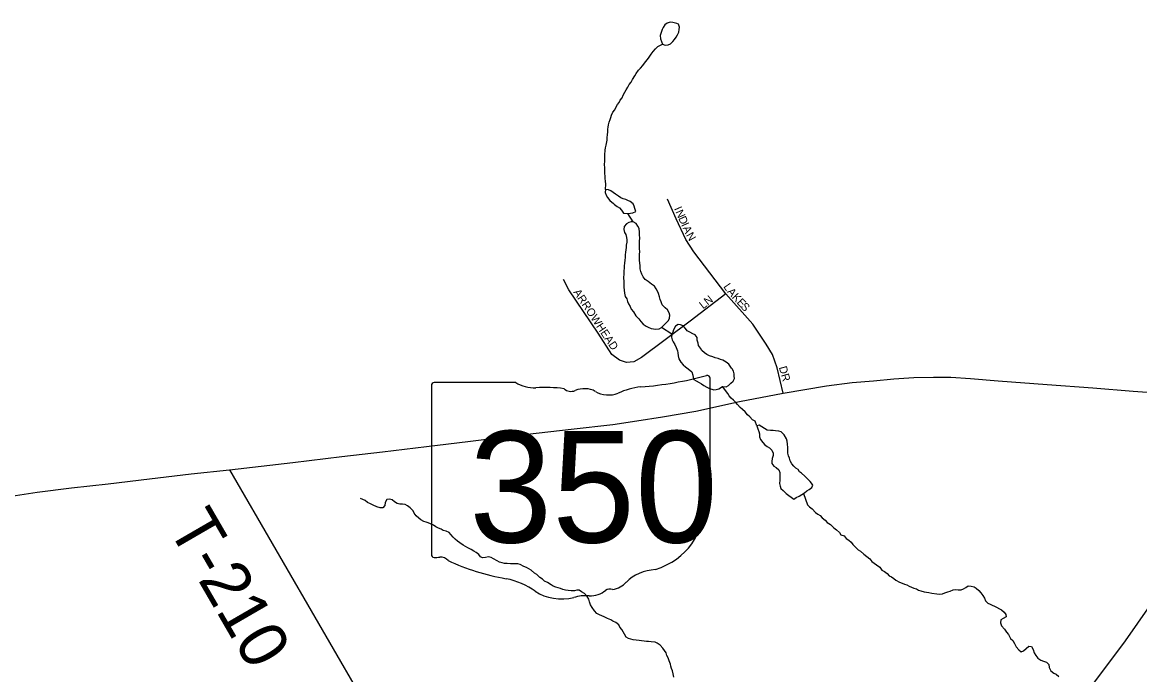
# Model space of a CAD drawing. Extents: x 0.4 to 34.4, y -2.1 to 19.9.
# Drawn here: x 7.097 to 8.419, y 12.657 to 13.429 of the extents above; entities that cross this region are included whole.
import ezdxf

# ---------------------------------------------------------------- set-up
doc = ezdxf.new("R2010")
doc.units = 0
for name, color, linetype in [('GM_X_Minor_Lake', 7, 'Continuous'), ('GM_X_Minor_River', 7, 'Continuous'), ('GM_X_State_Route', 7, 'Continuous'), ('GM_X_State_Shield', 7, 'Continuous'), ('GM_X_Township_Road', 7, 'Continuous'), ('GM_X_Township_Road_Text', 7, 'Continuous'), ('GM_X_Township_Subdivision', 7, 'Continuous'), ('GM_X_Township_Subdivision_Text', 7, 'Continuous'), ('GM_X_US_Route', 7, 'Continuous')]:
    doc.layers.add(name, color=color, linetype=linetype)

msp = doc.modelspace()

# ---------------------------------------------------------------- linework, layer by layer
at = {"layer": 'GM_X_Minor_Lake'}
msp.add_line((7.8082, 13.2034), (7.8131, 13.203), dxfattribs=at)
for points in [[(7.8714, 13.4279), (7.8666, 13.4291), (7.8632, 13.4292), (7.8597, 13.4281), (7.857, 13.4262), (7.855, 13.4232), (7.8538, 13.4206), (7.8526, 13.4172), (7.8514, 13.4134), (7.8521, 13.4096), (7.8542, 13.4035)], [(7.8542, 13.4035), (7.8576, 13.4023), (7.8611, 13.4026), (7.8638, 13.4037), (7.8665, 13.4063), (7.8684, 13.4089), (7.8704, 13.4115), (7.872, 13.4145), (7.8736, 13.4176), (7.8741, 13.4206), (7.8745, 13.4236), (7.8731, 13.4271), (7.8714, 13.4279)], [(7.8131, 13.203), (7.8165, 13.2033), (7.8192, 13.2036), (7.8227, 13.2054), (7.8216, 13.2089), (7.8209, 13.2116), (7.8195, 13.2143), (7.8161, 13.217), (7.8134, 13.2182), (7.8108, 13.2194), (7.8078, 13.2202), (7.8051, 13.2214), (7.8021, 13.2233), (7.7987, 13.226), (7.7961, 13.2276), (7.7931, 13.2296), (7.7905, 13.2311), (7.7867, 13.2312), (7.7866, 13.2278), (7.7877, 13.2247), (7.7891, 13.2217), (7.7921, 13.2182), (7.7964, 13.2147)], [(7.7964, 13.2147), (7.7977, 13.2135), (7.8007, 13.2112), (7.8033, 13.2096), (7.8056, 13.2069), (7.8082, 13.2034)], [(7.8622, 13.0854), (7.8601, 13.0891), (7.8575, 13.0914), (7.8541, 13.0949), (7.8527, 13.0984), (7.8516, 13.1011), (7.8509, 13.1045), (7.8495, 13.1083), (7.8484, 13.111), (7.8469, 13.1137), (7.8447, 13.1168), (7.8413, 13.1195), (7.8372, 13.1226), (7.8338, 13.125), (7.8316, 13.1281), (7.8298, 13.1311), (7.8287, 13.1342), (7.828, 13.1376), (7.8277, 13.1411), (7.8274, 13.1445), (7.8271, 13.1472), (7.8272, 13.1513), (7.8269, 13.1544), (7.8273, 13.1578), (7.827, 13.1612), (7.8271, 13.1647), (7.8272, 13.1704), (7.8273, 13.1738), (7.827, 13.1776), (7.8271, 13.181), (7.8268, 13.1852), (7.8253, 13.1879), (7.8231, 13.191), (7.8197, 13.1929), (7.8171, 13.193), (7.8144, 13.1923), (7.8117, 13.1908), (7.8089, 13.1874), (7.8085, 13.184), (7.8092, 13.1806), (7.811, 13.1779), (7.8117, 13.1745), (7.812, 13.1718), (7.812, 13.1691), (7.8115, 13.1653), (7.8114, 13.1627), (7.811, 13.16), (7.8105, 13.157), (7.8101, 13.1539), (7.81, 13.1513), (7.8096, 13.1475), (7.8095, 13.1444), (7.809, 13.1406), (7.809, 13.138), (7.8085, 13.1353), (7.8084, 13.1319), (7.8083, 13.1266), (7.8086, 13.1228), (7.8085, 13.1186), (7.8085, 13.1159), (7.8088, 13.1121), (7.8094, 13.1087), (7.8101, 13.1049), (7.812, 13.1018), (7.813, 13.0987), (7.8141, 13.096), (7.816, 13.093), (7.8174, 13.0899), (7.82, 13.0864), (7.8229, 13.0818), (7.8263, 13.0783), (7.8285, 13.0752), (7.8315, 13.0721), (7.8349, 13.0698), (7.8375, 13.0686), (7.8409, 13.067), (7.8436, 13.0666), (7.8462, 13.0662), (7.8504, 13.0665), (7.8531, 13.0679)], [(7.8531, 13.0679), (7.8613, 13.0762), (7.8625, 13.0792), (7.863, 13.0826), (7.8622, 13.0854)], [(7.9361, 13.02), (7.9326, 13.0246), (7.9296, 13.027), (7.9258, 13.0293), (7.9228, 13.0301), (7.9202, 13.0313), (7.9168, 13.0321), (7.9137, 13.0333), (7.91, 13.0346), (7.9066, 13.0361), (7.9039, 13.0381), (7.9009, 13.0408), (7.8991, 13.0435), (7.8969, 13.0466), (7.8966, 13.0493), (7.8955, 13.0531), (7.8952, 13.0561), (7.893, 13.0592), (7.8903, 13.0604), (7.8866, 13.0624), (7.8835, 13.0639), (7.8817, 13.067), (7.8787, 13.0701), (7.8757, 13.0713), (7.873, 13.0717), (7.8696, 13.0695), (7.8672, 13.0654), (7.8664, 13.0627), (7.8655, 13.0601), (7.8651, 13.0567), (7.8658, 13.0536), (7.8669, 13.0509), (7.8687, 13.0479), (7.8705, 13.0444), (7.872, 13.0406), (7.8723, 13.0379), (7.873, 13.0345), (7.8737, 13.031), (7.8759, 13.0272), (7.8788, 13.0237), (7.8814, 13.0214), (7.8848, 13.019), (7.8889, 13.0155), (7.89, 13.0117), (7.8907, 13.009), (7.8914, 13.0064), (7.894, 13.0048), (7.8978, 13.0028), (7.9004, 13.0012), (7.9031, 12.9993), (7.9068, 12.9973), (7.9098, 12.9957), (7.9125, 12.9949), (7.9151, 12.9941), (7.9178, 12.9945), (7.9209, 12.9955), (7.9251, 12.9981), (7.9297, 12.9977)], [(7.9297, 12.9977), (7.9324, 12.9995), (7.9352, 13.0021), (7.9379, 13.0044), (7.9395, 13.0078), (7.9392, 13.0104), (7.9392, 13.0131), (7.9381, 13.0165), (7.9367, 13.0192), (7.9361, 13.02)], [(8.029, 12.8858), (8.0226, 12.8921), (8.0189, 12.8956), (8.0163, 12.8972), (8.0148, 12.8999), (8.0122, 12.9014), (8.0096, 12.9041), (8.0073, 12.9068), (8.0055, 12.9103), (8.0044, 12.9134), (8.0034, 12.916), (8.0027, 12.9195), (8.0027, 12.9221), (8.0024, 12.926), (8.0021, 12.9298), (8.0018, 12.9336), (8.0011, 12.9363), (7.9982, 12.9409), (7.9948, 12.9444), (7.9918, 12.9452), (7.988, 12.9456), (7.9854, 12.9461), (7.9819, 12.9461), (7.9781, 12.9466), (7.9751, 12.9485), (7.9717, 12.9505), (7.9687, 12.9524), (7.966, 12.9517), (7.9671, 12.9483), (7.9682, 12.9448), (7.9689, 12.9422), (7.9692, 12.9387), (7.9702, 12.9353), (7.9728, 12.9318), (7.9754, 12.9291), (7.9781, 12.9272), (7.9807, 12.9256), (7.9837, 12.9229), (7.9851, 12.9194), (7.9851, 12.9164), (7.9842, 12.913), (7.9838, 12.9096), (7.9837, 12.9069), (7.9859, 12.9038), (7.9889, 12.9022), (7.9919, 12.8995), (7.993, 12.8965), (7.9933, 12.8938), (7.9933, 12.8907), (7.9932, 12.8873), (7.9927, 12.8835), (7.9934, 12.8801), (7.9941, 12.8774), (7.9971, 12.8751), (8.0005, 12.8716), (8.0095, 12.865)], [(8.0222, 12.8723), (8.0249, 12.8746), (8.028, 12.8764), (8.0311, 12.8786), (8.0323, 12.8813), (8.0305, 12.884), (8.029, 12.8858)], [(8.0095, 12.865), (8.0125, 12.8668), (8.016, 12.8683), (8.0222, 12.8723)]]:
    msp.add_lwpolyline(points, dxfattribs=at)
at = {"layer": 'GM_X_Minor_River'}
for points in [[(7.7867, 13.2312), (7.7872, 13.2377), (7.7869, 13.2411), (7.7866, 13.2442), (7.7863, 13.2472), (7.7859, 13.2503), (7.786, 13.2537), (7.7861, 13.2571), (7.7858, 13.2609), (7.7859, 13.2647), (7.786, 13.2693), (7.7861, 13.2723), (7.7866, 13.278), (7.787, 13.2807), (7.7875, 13.2837), (7.7887, 13.2898), (7.7888, 13.2924), (7.7893, 13.2966), (7.7897, 13.2993), (7.7898, 13.3027), (7.7899, 13.3053), (7.7903, 13.308), (7.7911, 13.311), (7.7923, 13.314), (7.7932, 13.3167), (7.794, 13.3193), (7.7956, 13.3227), (7.7979, 13.3257), (7.7992, 13.3284), (7.8011, 13.3318), (7.8031, 13.3344), (7.8043, 13.337), (7.8066, 13.3397), (7.8079, 13.3431), (7.8099, 13.3464), (7.8114, 13.3491), (7.8134, 13.3525), (7.815, 13.3555), (7.8174, 13.3585), (7.819, 13.3615), (7.8217, 13.366), (7.8233, 13.3686), (7.8261, 13.3724), (7.8284, 13.375), (7.8312, 13.378), (7.8343, 13.3825), (7.8367, 13.3851), (7.8386, 13.3881), (7.841, 13.3915), (7.8433, 13.3945), (7.8461, 13.3979), (7.8488, 13.4005), (7.8542, 13.4035)], [(7.8082, 13.2034), (7.8131, 13.203)], [(7.8197, 13.1929), (7.8131, 13.203)], [(7.8655, 13.0601), (7.8531, 13.0679)], [(7.966, 12.9517), (7.9639, 12.9571), (7.9609, 12.9587), (7.9575, 12.9622), (7.9549, 12.9645), (7.9519, 12.9683), (7.9489, 12.9711), (7.9463, 12.9734), (7.943, 12.9769), (7.9407, 12.9796), (7.9381, 12.9819), (7.9355, 12.9846), (7.9333, 12.9873), (7.9314, 12.99), (7.9251, 12.9981)], [(7.5659, 12.8423), (7.5629, 12.845), (7.5607, 12.8485), (7.5592, 12.8511), (7.5559, 12.8546), (7.5525, 12.857), (7.5499, 12.8585), (7.5468, 12.859), (7.5434, 12.859), (7.5404, 12.8599), (7.5374, 12.8618), (7.5344, 12.8642), (7.5317, 12.865), (7.5283, 12.8643), (7.5263, 12.8609), (7.5258, 12.8575), (7.5235, 12.8545), (7.5201, 12.8545), (7.5163, 12.8557), (7.5121, 12.8577), (7.5087, 12.8593), (7.5053, 12.8609), (7.5027, 12.8632), (7.4997, 12.8644), (7.497, 12.8656)], [(8.021, 12.8717), (8.0257, 12.8582), (8.0283, 12.8559), (8.0313, 12.8535), (8.0354, 12.8493), (8.038, 12.8473), (8.0407, 12.8454), (8.0433, 12.8427), (8.0466, 12.8399), (8.0492, 12.8372), (8.053, 12.8349), (8.0571, 12.831), (8.0601, 12.8286), (8.0635, 12.8255), (8.0653, 12.8228), (8.0691, 12.8213), (8.0717, 12.8185), (8.0747, 12.8162), (8.0773, 12.8139), (8.0795, 12.8112), (8.0833, 12.8073), (8.0859, 12.805), (8.0885, 12.8034), (8.0926, 12.7999), (8.096, 12.7972), (8.0994, 12.7941), (8.102, 12.791), (8.1046, 12.789), (8.1076, 12.7871), (8.1113, 12.7843), (8.1139, 12.7809), (8.1169, 12.7793), (8.1199, 12.777), (8.1225, 12.7742), (8.1252, 12.7731), (8.1278, 12.7711), (8.1304, 12.7692), (8.1346, 12.7668), (8.138, 12.7656), (8.1406, 12.7644), (8.1433, 12.7636), (8.1463, 12.762), (8.1489, 12.7608), (8.1516, 12.7596), (8.1546, 12.7588), (8.1572, 12.7572), (8.1599, 12.7564), (8.1637, 12.7552), (8.1667, 12.7548), (8.1694, 12.7544), (8.1728, 12.7535), (8.1789, 12.7527), (8.1819, 12.7526), (8.1854, 12.7529), (8.1884, 12.754), (8.1919, 12.7551), (8.1946, 12.7562), (8.198, 12.7576), (8.2007, 12.758), (8.2041, 12.7575), (8.2076, 12.7575), (8.2103, 12.7586), (8.213, 12.7604), (8.2161, 12.7623), (8.2195, 12.7618), (8.2229, 12.761), (8.2255, 12.7594), (8.2285, 12.7567), (8.2308, 12.754), (8.2333, 12.7509), (8.2352, 12.7478), (8.2363, 12.7444), (8.2392, 12.7417), (8.2419, 12.7405), (8.2494, 12.7369), (8.2528, 12.7353), (8.2555, 12.7341), (8.2584, 12.731), (8.2603, 12.7283), (8.261, 12.7257), (8.2575, 12.7238), (8.2544, 12.722), (8.2543, 12.7186), (8.2554, 12.7151), (8.2588, 12.7109), (8.2613, 12.7074), (8.2636, 12.7047), (8.2661, 12.7001), (8.2688, 12.6978), (8.2709, 12.6939), (8.2728, 12.6901), (8.2757, 12.6866), (8.2787, 12.6843), (8.2814, 12.6854), (8.2846, 12.6883), (8.2877, 12.6909), (8.2907, 12.6905), (8.2929, 12.687), (8.294, 12.6832), (8.2958, 12.6798), (8.2984, 12.6767)], [(7.8596, 12.6798), (7.8586, 12.6832), (7.8567, 12.6859), (7.8545, 12.6886), (7.8515, 12.6921), (7.8481, 12.6944), (7.8455, 12.6956), (7.8409, 12.6961), (7.8379, 12.6965), (7.8352, 12.6966), (7.8326, 12.697), (7.8295, 12.6971), (7.8265, 12.6975), (7.8231, 12.6979), (7.8196, 12.6984), (7.817, 12.6992), (7.814, 12.7), (7.8113, 12.7016), (7.8095, 12.705), (7.8076, 12.7077), (7.8062, 12.7108), (7.804, 12.7135), (7.8025, 12.7162), (7.7991, 12.7189), (7.7957, 12.7205), (7.7931, 12.7221), (7.7893, 12.7237), (7.7852, 12.7256), (7.7825, 12.7268), (7.7799, 12.728), (7.7765, 12.7296), (7.7739, 12.7327), (7.7709, 12.7366), (7.7691, 12.74), (7.768, 12.7435), (7.767, 12.7465), (7.7651, 12.7496), (7.7622, 12.7531), (7.7584, 12.7554), (7.7558, 12.757), (7.7531, 12.757), (7.75, 12.7563), (7.7462, 12.7564), (7.7428, 12.7569), (7.7394, 12.7573), (7.7363, 12.7581), (7.7337, 12.7593), (7.7307, 12.7601), (7.728, 12.7609), (7.725, 12.7621), (7.7224, 12.7637), (7.7182, 12.7661), (7.7148, 12.768), (7.7122, 12.7704), (7.7092, 12.7723), (7.7055, 12.7758), (7.7028, 12.7774), (7.6991, 12.7809), (7.6935, 12.784), (7.6901, 12.7852), (7.6859, 12.7876), (7.6833, 12.7884), (7.6802, 12.7884), (7.6772, 12.7885), (7.6745, 12.7885), (7.6707, 12.7886), (7.6673, 12.7887), (7.6646, 12.7895), (7.6616, 12.7903), (7.6586, 12.7919), (7.6544, 12.7942), (7.6518, 12.7958), (7.6484, 12.7966), (7.6449, 12.7959), (7.6415, 12.7956), (7.6388, 12.7968), (7.637, 12.7995), (7.634, 12.8018), (7.631, 12.8034), (7.628, 12.8054), (7.6242, 12.8073), (7.6212, 12.8089), (7.6186, 12.8105), (7.6144, 12.8132), (7.6118, 12.8152), (7.6092, 12.8175), (7.6066, 12.8198), (7.604, 12.8229), (7.6018, 12.8256), (7.5984, 12.8272), (7.5949, 12.828), (7.5923, 12.8292), (7.5893, 12.8304), (7.5863, 12.832), (7.5833, 12.834), (7.5799, 12.8356), (7.5772, 12.8367), (7.5746, 12.8376), (7.5719, 12.8384), (7.5685, 12.8403), (7.5659, 12.8423)], [(7.8678, 12.6541), (7.8668, 12.658), (7.8661, 12.6618), (7.865, 12.6645), (7.8643, 12.6671), (7.8636, 12.6698), (7.8622, 12.6736), (7.8611, 12.6771), (7.8596, 12.6798)], [(8.2984, 12.6767), (8.3018, 12.6743), (8.3052, 12.6731), (8.3086, 12.6719), (8.3112, 12.6692), (8.3119, 12.6658), (8.3137, 12.6619), (8.3174, 12.6588), (8.3201, 12.6576), (8.3231, 12.6549)]]:
    msp.add_lwpolyline(points, dxfattribs=at)
at = {"layer": 'GM_X_State_Route'}
msp.add_lwpolyline([(7.0734, 12.8667), (7.1144, 12.8731), (7.155, 12.8784), (7.1986, 12.8829), (7.2475, 12.8888), (7.2968, 12.8948), (7.3419, 12.8996), (7.417, 12.9083), (7.475, 12.9153), (7.5231, 12.9209), (7.5751, 12.9272), (7.624, 12.9331), (7.6809, 12.9401), (7.7461, 12.9478), (7.7954, 12.9534), (7.8238, 12.9576), (7.8542, 12.9623), (7.8936, 12.9691), (7.9453, 12.9806), (7.9969, 12.9905), (8.0482, 12.999), (8.0787, 13.0029), (8.1041, 13.0048), (8.128, 13.0072), (8.1515, 13.0089), (8.175, 13.0094), (8.1955, 13.0092), (8.2185, 13.0075), (8.2515, 13.0049), (8.3094, 13.0005), (8.3635, 12.9965), (8.4112, 12.9926), (8.4611, 12.9891)], dxfattribs=at)
at = {"layer": 'GM_X_State_Shield'}
for p, q in [((7.9106, 12.9033), (7.9106, 13.008)), ((7.581, 12.9996), (7.581, 12.7994)), ((7.6807, 13.003), (7.5842, 13.003)), ((7.9105, 12.9033), (7.9106, 12.9033))]:
    msp.add_line(p, q, dxfattribs=at)
for centre, major_axis, start_param, end_param in [((7.7932, 13.2758), (0.3495, 0), 4.814394, 5.042369), ((7.9069, 13.0084), (0.00367, 0), 6.141152, 7.989035), ((7.5848, 13), (0.00382, 0), 1.712693, 3.28349), ((7.7037, 13.0262), (0.037, 0), 4.042523, 4.731795), ((7.716, 12.8907), (0.133, 0), 1.404758, 1.657858), ((7.7462, 13.001), (0.0107, 0), 3.836095, 5.185415), ((7.7619, 12.9779), (0.0222, 0), 0.950623, 2.079405), ((7.8377, 12.9419), (0.0703, 0), 1.699011, 2.107814), ((7.7906, 13.0096), (0.0267, 0), 4.081561, 5.145723), ((7.9067, 12.9029), (0.00393, 0), 5.05454, 6.418171), ((7.9097, 12.8956), (0.00568, 0), 1.883978, 3.671073), ((7.8736, 12.8824), (0.0341, 0), 5.934695, 6.695948), ((7.9237, 12.8595), (0.0248, 0), 2.387724, 3.262537), ((7.8127, 12.8462), (0.0874, 0), 5.101752, 6.440018), ((7.5848, 12.799), (0.00385, 0), 3.00124, 4.508301), ((7.5854, 12.8195), (0.0294, 0), 4.665946, 4.897461), ((7.5914, 12.7879), (0.0106, 0), 0.519207, 1.627899), ((7.7252, 12.9677), (0.2524, 0), 4.195997, 4.488961), ((7.65, 12.7095), (0.079, 0), 0.823519, 1.323587), ((7.8496, 12.7433), (0.0479, 0), 1.647645, 2.488434), ((7.7354, 12.7869), (0.0501, 0), 4.026481, 4.996735), ((7.768, 12.7719), (0.0267, 0), 4.691044, 5.507374), ((7.7921, 12.7525), (0.00752, 0), 1.147584, 2.315152), ((7.7889, 12.78), (0.0282, 0), 4.937069, 5.64225), ((7.7643, 12.7177), (0.0412, 0), 1.495662, 1.94098)]:
    msp.add_ellipse(centre, major_axis=major_axis, ratio=0.8, start_param=start_param, end_param=end_param, dxfattribs=at)
at = {"layer": 'GM_X_Township_Road'}
msp.add_lwpolyline([(7.3419, 12.8996), (7.7257, 12.237), (7.7391, 12.2208), (7.751, 12.2088), (7.7586, 12.2008), (7.7702, 12.1721), (7.8386, 12.0698)], dxfattribs=at)
at = {"layer": 'GM_X_Township_Subdivision'}
for points in [[(7.9969, 12.9905), (7.9898, 13.0204), (7.9844, 13.036), (7.9769, 13.0482), (7.9613, 13.0719), (7.9294, 13.1079), (7.8914, 13.1574), (7.882, 13.1723), (7.8704, 13.1967), (7.8603, 13.2198)], [(7.9294, 13.1079), (7.887, 13.0755), (7.8295, 13.0325), (7.8202, 13.0273), (7.8119, 13.0268), (7.8036, 13.0293), (7.7943, 13.0361), (7.7782, 13.0615), (7.7435, 13.1128), (7.7373, 13.1247)]]:
    msp.add_lwpolyline(points, dxfattribs=at)
at = {"layer": 'GM_X_US_Route'}
msp.add_lwpolyline([(7.9931, 12.1913), (7.9976, 12.1948), (8.0316, 12.2202), (8.0496, 12.2375), (8.071, 12.2589), (8.0891, 12.2752), (8.1165, 12.3008), (8.1279, 12.3125), (8.1391, 12.3275), (8.1644, 12.3629), (8.2005, 12.4129), (8.2447, 12.4746), (8.2869, 12.534), (8.3265, 12.5897), (8.3657, 12.6487), (8.4022, 12.6972), (8.4429, 12.7559)], dxfattribs=at)

# ---------------------------------------------------------------- texts
at = {"layer": 'GM_X_State_Shield'}
msp.add_text('350', height=0.13184, dxfattribs=at).set_placement((7.6257, 12.8136))
at = {"layer": 'GM_X_Township_Road_Text'}
msp.add_text('T-210', height=0.05682, rotation=300.0947, dxfattribs=at).set_placement((7.2682, 12.8318))
at = {"layer": 'GM_X_Township_Subdivision_Text'}
for s, rotation, p in [('I', 294.14, (7.8677, 13.2087)), ('N', 294.14, (7.8694, 13.2049)), ('D', 294.14, (7.8728, 13.1973)), ('I', 294.1767, (7.8762, 13.1897)), ('A', 294.16, (7.8779, 13.1859)), ('N', 299.6014, (7.8818, 13.1774)), ('L', 304.607, (7.9259, 13.1164)), ('A', 310.0934, (7.9303, 13.1101)), ('ARROWHEAD', 303.6894, (7.7484, 13.1098)), ('LN', 38.6634, (7.9024, 13.0894)), ('K', 312.4198, (7.9359, 13.1035)), ('E', 312.4676, (7.9415, 13.0973)), ('S', 312.4299, (7.946, 13.0924)), ('DR', 285.5291, (7.9919, 13.0209))]:
    msp.add_text(s, height=0.00947, rotation=rotation, dxfattribs=at).set_placement(p)

doc.saveas('drawing.dxf')
